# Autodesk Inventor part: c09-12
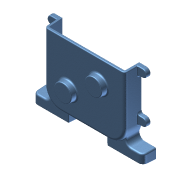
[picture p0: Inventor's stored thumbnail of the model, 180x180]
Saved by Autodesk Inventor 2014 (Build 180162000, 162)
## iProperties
Created: 2008-05
Part Number: c09-12
Material: Aluminum 6061
Document SubType Name: Modeling
Designer: Thom Tremblay
Mass: 2781.62 g
Surface Area: 1986.38 cm^2
Volume: 1026.43 cm^3
Density: 2.71 g/cm^3
Appearance: Steel - Cast
Author: Thom Tremblay
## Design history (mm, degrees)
sketch "Sketch1"
  geometry: L1 (-127, 208.28)-(0, 208.28); L2 (127, 208.28)-(127, 0); L3 (0, 0)-(-127, 0); L4 (-127, 0)-(-127, 208.28); L5 (0, 0)-(0, 208.28); L6 (0, 208.28)-(127, 208.28); L7 (0, 0)-(127, 0); 1 further point
  constraints: 14 end point, 3 parallel, 2 perpendicular, 1 coincident, 1 horizontal
  dimensions: "d0" = 254 distance of L1.start L2.start; "d1" = 208.28 distance of L3.end L1.start
extrude "Extrusion1" new body sketch "Sketch1" distance "d2" = 50.8; taper "d3" = 0 deg
feature "FaceDraft1" dims angle "d60" = 2 deg
fillet "Fillet1" dims "d10" = 50.8
fillet "Fillet2" dims "d11" = 10.16
shell "Shell1" dims "d12" = 7.62
sketch "Sketch3"
  geometry: L1 (58.42, 3.81)-(58.42, -27.94); L2 (58.42, -27.94)-(172.72, -27.94); L3 (172.72, -27.94)-(172.72, 3.81); L4 (172.72, 3.81)-(58.42, 3.81); L5 (127, 50.769)-(127, 208.28) reference; L6 (0, 0)-(76.231, 0) reference; 1 further point
  constraints: 8 end point, 2 parallel, 1 perpendicular, 1 vertical
  dimensions: "d13" = 31.75 distance of L2.end L3.end; "d14" = 45.72 distance between parallel lines of L5 L3; "d15" = 27.94 distance between parallel lines of L6 L2; "d16" = 114.3 distance of L1.end L2.end
extrude "Extrusion3" join sketch "Sketch3" distance "d17" = 40.64; taper "d18" = -2 deg
fillet "Fillet16" dims "d61" = 17.78
fillet "Fillet26" dims "d73" = 15.24
sketch "Sketch5"
  geometry: L1 (127, 50.769)-(127, 208.28) reference; L2 (127, 208.28)-(119.375, 208.28) reference; L3 (0, 0)-(58.42, 0) reference; L4 (58.42, 0)-(58.42, -27.94) reference; L5 (127, 208.28)-(142.24, 208.28); L6 (142.24, 182.88)-(127, 182.88); L7 (30.48, 0)-(30.48, -10.16); L8 (43.18, -22.86)-(58.42, -22.86); L9 (127, 50.769)-(142.24, 50.769); L10 (142.24, 76.169)-(127, 76.169); A1 r 12.7 centre (142.24, 195.58) between (142.24, 182.88) and (142.24, 208.28); A2 r 12.7 centre (43.18, -10.16) between (30.48, -10.16) and (43.18, -22.86); A3 r 12.7 centre (142.24, 63.469) between (142.24, 50.769) and (142.24, 76.169); 4 further points; 1 other entity
  constraints: 12 end point, 6 point on circle, 6 tangent, 5 perpendicular, 4 point on line, 3 centre point, 2 parallel, 1 equal radius, 1 other
  dimensions: "d34" = 12.7 radius of A1; "d35" = 15.24 distance of L1.end L5.end; "d37" = 12.7 radius of A2; "d38" = 15.24 distance of L8.start L8.end; "d59" = 10.16 distance of L7.start L7.end
extrude "Extrusion5" join sketch "Sketch5" distance "d40" = 12.7; taper "d41" = -2 deg
extrude "Extrusion7" join sketch "Sketch5" stored distance "d47" = 12.7; taper "d48" = -2 deg
extrude "Extrusion8" join sketch "Sketch5" stored distance "d50" = 12.7; taper "d51" = -2 deg
fillet "Fillet17" dims "d62" = 7.62
fillet "Fillet18" dims "d64" = 2.54
fillet "Fillet19" dims "d65" = 2.54
fillet "Fillet22" dims "d68" = 2.54
fillet "Fillet25" dims "d71" = 2.54
fillet "Fillet27" dims "d74" = 5.08
fillet "Fillet31" dims "d78" = 2.54
fillet "Fillet32" dims "d79" = 2.54
mirror "Mirror3"
sketch "Sketch4"
  geometry: L1 (-127, 50.769)-(-127, 182.88) reference; L2 (-142.24, 208.28)-(-119.375, 208.28) reference; L3 (-50.8, 73.66)-(44.238, 137.16); C1 r 27.94 at (-50.8, 73.66); C2 r 27.94 at (44.238, 137.16); 1 further point
  constraints: 2 centre point, 2 end point, 1 equal radius
  dimensions: "d22" = 95.0381 horizontal distance of L3.end L3.start (derived); "d23" = 76.2 distance from line of L1 L3.start; "d24" = 63.5 vertical distance of L3.end L3.start; "d27" = 55.88 diameter of C2; "d72" = 134.62 distance from line of L2 L3.start; "d80" = 114.3 distance of L3.start L3.end
extrude "Extrusion4" join sketch "Sketch4" distance "d28" = 17.78; taper "d29" = -2 deg
fillet "Fillet5" dims "d30" = 2.54, "d31" = 5.08
workplane "Work Plane2"
sketch "Sketch7"
  geometry: L1 (0, 0)-(0.906, 25.948) reference; L2 (107.89, 38.212)-(109.223, 0) reference; L3 (100.134, 5.546)-(99.441, 25.4); L4 (99.441, 25.4)-(39.287, 25.4); L5 (29.635, 15.748)-(29.635, 1.955); A1 r 9.652 centre (39.287, 15.748) between (39.287, 25.4) and (29.635, 15.748); 3 further points; 1 other entity
  constraints: 6 end point, 2 point on circle, 2 tangent, 1 centre point, 1 horizontal, 1 parallel, 1 other
  dimensions: "d91" = 9.652 radius of A1; "d92" = 8.89 distance between parallel lines of L2 L3; "d93" = 2 deg angle of L5 L1; "d94" = 25.4 distance from line of L2.end L4
extrude "Extrusion9" cut sketch "Sketch7" distance "d96" = 15.875; taper "d97" = -2 deg
mirror "Mirror4"
fillet "Fillet35" dims "d100" = 6.35, "d101" = 2.54
fillet "Fillet36" dims "d102" = 0.762
sketch "Rib Sketch"
  geometry: L1 (-21.093, 93.509)-(15.839, 118.185); C1 r 27.405 at (-50.8, 73.66) reference; C2 r 27.405 at (44.238, 137.16) reference; 1 further point
  constraints: 2 end point, 2 point on line
feature "Rib1" sketch "Rib Sketch" dims "d82" = 7.62, "d83" = 2.54, "d84" = 5 deg, "d85" = 0, "d86" = 2.54, "d87" = 2.54
fillet "Fillet33" dims "d88" = 3.048
body "Solid1"
other parameters: "d42" = 7.62, "d46" = 12.7, "d49" = 12.7, "d81" = 10.16, "d95" = 15.875
